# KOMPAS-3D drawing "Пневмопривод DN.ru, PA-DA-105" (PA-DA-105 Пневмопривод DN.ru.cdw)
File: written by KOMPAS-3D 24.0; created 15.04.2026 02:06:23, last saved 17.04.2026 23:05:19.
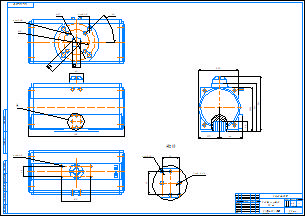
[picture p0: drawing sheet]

Document properties: Автор: DN.ru; Форматы листов документа: A1; Полное имя файла: PA-DA-105 Пневмопривод DN.ru.m3d; Масса: 6.8; Наименование: Пневмопривод DN.ru; Количество листов документа: 1; Примечание: D290-00296

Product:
- Part/product: Пневмопривод DN.ru  | designation PA-DA-105
    Масса: 6.8
    Раздел спецификации: Прочие изделия
    Примечание: D290-00296

Views: Вид 1, Вид:1, Проекционный вид 2, Выносной элемент 6, Выносной элемент А, Выносной элемент
Referenced files in C:\Работа\PA-DA-х Пневмопривод DN.ru\052\: PA-DA-052 Пневмопривод DN.ru.m3d
Referenced files in C:\Работа\PA-DA-х Пневмопривод DN.ru\105\: PA-DA-105 Пневмопривод DN.ru.m3d
Referenced files in C:\Program Files\ASCON\KOMPAS-3D v24\Templates\: Чертеж_DN.ru.cdt
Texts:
  objid
  viewid
  PA-DA-105
  Чертеж_DN.ru.cdt
  Пневмопривод
  Пневмопривод DN.ru
  PA-DA-105 Пневмопривод DN.ru
Dimensions and other numbers on the sheet: 0; 3; 2; 4; 40; 608; 268; 9; 4 отв.; 10; 22; 102; 70; 8; 7; 1; 2 отв.; 24; 32; 5; 1:1; 6,8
